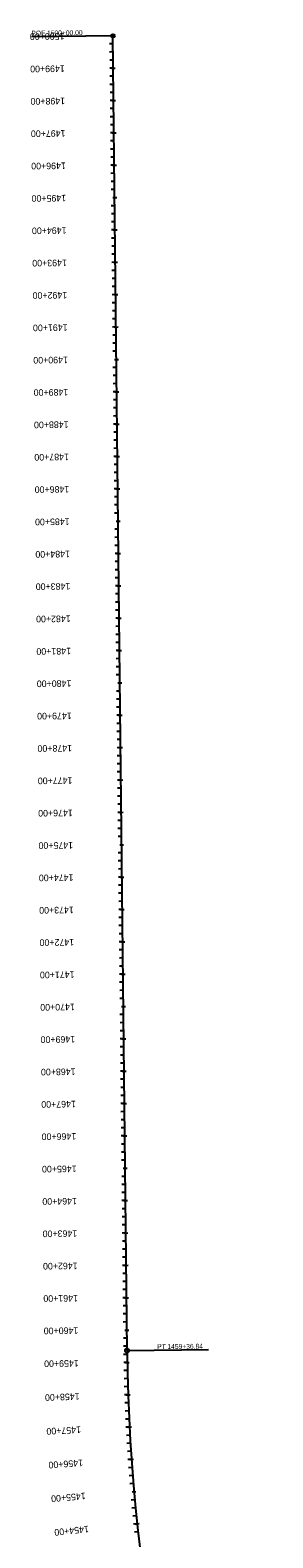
# Model space of a CAD drawing. Extents: x 20505176 to 20507193, y 7960287 to 7982631.
# Drawn here: x 20505176 to 20505926, y 7977971 to 7982631 of the extents above; entities that cross this region are included whole.
import ezdxf

# ---------------------------------------------------------------- set-up
doc = ezdxf.new("R2010")
doc.units = 0
for name, color, linetype in [('Alignment', 7, 'Continuous'), ('TextAlignment', 7, 'Continuous'), ('TextAlignmentLrg', 7, 'Continuous'), ('TextAlignmentSml', 7, 'Continuous')]:
    doc.layers.add(name, color=color, linetype=linetype)

msp = doc.modelspace()

# ---------------------------------------------------------------- linework, layer by layer
at = {"layer": 'Alignment'}
msp.add_line((20505475.7, 7978550.4), (20505432.2, 7982613.3), dxfattribs=at)
msp.add_arc((20511205.4, 7978611.7), 5730, 180.61343, 202.8772, dxfattribs=at)
at = {"layer": 'TextAlignment'}
for p, q in [((20505432.2, 7982613.3), (20505180.2, 7982610.6)), ((20505180.2, 7982610.6), (20505180.2, 7982610.6)), ((20505475.7, 7978550.4), (20505727.7, 7978553.1)), ((20505727.7, 7978553.1), (20505727.7, 7978553.1))]:
    msp.add_line(p, q, dxfattribs=at)
for centre, radius in [((20505432.2, 7982613.3), 5.34), ((20505475.7, 7978550.4), 6.24)]:
    msp.add_circle(centre, radius, dxfattribs=at)
at = {"layer": 'TextAlignmentLrg'}
for p, q in [((20505426, 7982613.2), (20505438.3, 7982613.4)), ((20505433.2, 7982513.3), (20505422.3, 7982513.2)), ((20505434.3, 7982413.3), (20505423.4, 7982413.2)), ((20505435.4, 7982313.3), (20505424.5, 7982313.2)), ((20505436.5, 7982213.3), (20505425.5, 7982213.2)), ((20505431.4, 7982113.3), (20505443.6, 7982113.4)), ((20505438.6, 7982013.3), (20505427.7, 7982013.2)), ((20505439.7, 7981913.3), (20505428.8, 7981913.2)), ((20505440.7, 7981813.3), (20505429.8, 7981813.2)), ((20505441.8, 7981713.4), (20505430.9, 7981713.2)), ((20505436.8, 7981613.3), (20505449, 7981613.4)), ((20505444, 7981513.4), (20505433, 7981513.2)), ((20505445, 7981413.4), (20505434.1, 7981413.3)), ((20505446.1, 7981313.4), (20505435.2, 7981313.3)), ((20505447.2, 7981213.4), (20505436.3, 7981213.3)), ((20505442.1, 7981113.3), (20505454.4, 7981113.5)), ((20505449.3, 7981013.4), (20505438.4, 7981013.3)), ((20505450.4, 7980913.4), (20505439.5, 7980913.3)), ((20505451.5, 7980813.4), (20505440.5, 7980813.3)), ((20505452.5, 7980713.4), (20505441.6, 7980713.3)), ((20505447.5, 7980613.3), (20505459.7, 7980613.5)), ((20505454.7, 7980513.4), (20505443.8, 7980513.3)), ((20505455.8, 7980413.4), (20505444.8, 7980413.3)), ((20505456.8, 7980313.4), (20505445.9, 7980313.3)), ((20505457.9, 7980213.4), (20505447, 7980213.3)), ((20505452.9, 7980113.4), (20505465.1, 7980113.5)), ((20505460, 7980013.4), (20505449.1, 7980013.3)), ((20505461.1, 7979913.5), (20505450.2, 7979913.3)), ((20505462.2, 7979813.5), (20505451.3, 7979813.3)), ((20505463.3, 7979713.5), (20505452.3, 7979713.3)), ((20505458.2, 7979613.4), (20505470.5, 7979613.5)), ((20505465.4, 7979513.5), (20505454.5, 7979513.4)), ((20505466.5, 7979413.5), (20505455.6, 7979413.4)), ((20505467.6, 7979313.5), (20505456.6, 7979313.4)), ((20505468.6, 7979213.5), (20505457.7, 7979213.4)), ((20505463.6, 7979113.4), (20505475.8, 7979113.6)), ((20505470.8, 7979013.5), (20505459.8, 7979013.4)), ((20505471.8, 7978913.5), (20505460.9, 7978913.4)), ((20505472.9, 7978813.5), (20505462, 7978813.4)), ((20505474, 7978713.5), (20505463.1, 7978713.4)), ((20505468.9, 7978613.5), (20505481.2, 7978613.6)), ((20505476.2, 7978513.5), (20505465.3, 7978513.3)), ((20505478.8, 7978413.6), (20505467.9, 7978413.2)), ((20505483.2, 7978313.7), (20505472.3, 7978313.1)), ((20505489.2, 7978213.9), (20505478.3, 7978213.1)), ((20505491, 7978113.6), (20505503.1, 7978114.7)), ((20505506.6, 7978014.6), (20505495.7, 7978013.5))]:
    msp.add_line(p, q, dxfattribs=at)
at = {"layer": 'TextAlignmentSml'}
for p, q in [((20505426, 7982613.2), (20505438.3, 7982613.4)), ((20505432.4, 7982588.3), (20505421.5, 7982588.2)), ((20505432.7, 7982563.3), (20505421.8, 7982563.2)), ((20505433, 7982538.3), (20505422.1, 7982538.2)), ((20505433.5, 7982488.3), (20505422.6, 7982488.2)), ((20505427.1, 7982513.2), (20505439.4, 7982513.4)), ((20505433.8, 7982463.3), (20505422.9, 7982463.2)), ((20505434, 7982438.3), (20505423.1, 7982438.2)), ((20505434.6, 7982388.3), (20505423.7, 7982388.2)), ((20505428.2, 7982413.2), (20505440.4, 7982413.4)), ((20505434.8, 7982363.3), (20505423.9, 7982363.2)), ((20505435.1, 7982338.3), (20505424.2, 7982338.2)), ((20505435.7, 7982288.3), (20505424.7, 7982288.2)), ((20505429.3, 7982313.3), (20505441.5, 7982313.4)), ((20505435.9, 7982263.3), (20505425, 7982263.2)), ((20505436.2, 7982238.3), (20505425.3, 7982238.2)), ((20505430.3, 7982213.3), (20505442.6, 7982213.4)), ((20505436.7, 7982188.3), (20505425.8, 7982188.2)), ((20505437, 7982163.3), (20505426.1, 7982163.2)), ((20505437.3, 7982138.3), (20505426.3, 7982138.2)), ((20505431.4, 7982113.3), (20505443.6, 7982113.4)), ((20505437.8, 7982088.3), (20505426.9, 7982088.2)), ((20505438.1, 7982063.3), (20505427.1, 7982063.2)), ((20505438.3, 7982038.3), (20505427.4, 7982038.2)), ((20505432.5, 7982013.3), (20505444.7, 7982013.4)), ((20505438.9, 7981988.3), (20505427.9, 7981988.2)), ((20505439.1, 7981963.3), (20505428.2, 7981963.2)), ((20505439.4, 7981938.3), (20505428.5, 7981938.2)), ((20505433.6, 7981913.3), (20505445.8, 7981913.4)), ((20505439.9, 7981888.3), (20505429, 7981888.2)), ((20505440.2, 7981863.3), (20505429.3, 7981863.2)), ((20505440.5, 7981838.3), (20505429.6, 7981838.2)), ((20505441, 7981788.3), (20505430.1, 7981788.2)), ((20505434.6, 7981813.3), (20505446.9, 7981813.4)), ((20505441.3, 7981763.3), (20505430.4, 7981763.2)), ((20505441.5, 7981738.3), (20505430.6, 7981738.2)), ((20505442.1, 7981688.4), (20505431.2, 7981688.2)), ((20505435.7, 7981713.3), (20505447.9, 7981713.4)), ((20505442.4, 7981663.4), (20505431.4, 7981663.2)), ((20505442.6, 7981638.4), (20505431.7, 7981638.2)), ((20505443.2, 7981588.4), (20505432.2, 7981588.2)), ((20505436.8, 7981613.3), (20505449, 7981613.4)), ((20505443.4, 7981563.4), (20505432.5, 7981563.2)), ((20505443.7, 7981538.4), (20505432.8, 7981538.2)), ((20505437.8, 7981513.3), (20505450.1, 7981513.4)), ((20505444.2, 7981488.4), (20505433.3, 7981488.2)), ((20505444.5, 7981463.4), (20505433.6, 7981463.2)), ((20505444.8, 7981438.4), (20505433.8, 7981438.2)), ((20505438.9, 7981413.3), (20505451.2, 7981413.4)), ((20505445.3, 7981388.4), (20505434.4, 7981388.3)), ((20505445.6, 7981363.4), (20505434.7, 7981363.3)), ((20505445.8, 7981338.4), (20505434.9, 7981338.3)), ((20505440, 7981313.3), (20505452.2, 7981313.4)), ((20505446.4, 7981288.4), (20505435.5, 7981288.3)), ((20505446.6, 7981263.4), (20505435.7, 7981263.3)), ((20505446.9, 7981238.4), (20505436, 7981238.3)), ((20505447.4, 7981188.4), (20505436.5, 7981188.3)), ((20505441.1, 7981213.3), (20505453.3, 7981213.4)), ((20505447.7, 7981163.4), (20505436.8, 7981163.3)), ((20505448, 7981138.4), (20505437.1, 7981138.3)), ((20505448.5, 7981088.4), (20505437.6, 7981088.3)), ((20505442.1, 7981113.3), (20505454.4, 7981113.5)), ((20505448.8, 7981063.4), (20505437.9, 7981063.3)), ((20505449.1, 7981038.4), (20505438.1, 7981038.3)), ((20505449.6, 7980988.4), (20505438.7, 7980988.3)), ((20505443.2, 7981013.3), (20505455.4, 7981013.5)), ((20505449.9, 7980963.4), (20505438.9, 7980963.3)), ((20505450.1, 7980938.4), (20505439.2, 7980938.3)), ((20505450.7, 7980888.4), (20505439.7, 7980888.3)), ((20505444.3, 7980913.3), (20505456.5, 7980913.5)), ((20505450.9, 7980863.4), (20505440, 7980863.3)), ((20505451.2, 7980838.4), (20505440.3, 7980838.3)), ((20505445.3, 7980813.3), (20505457.6, 7980813.5)), ((20505451.7, 7980788.4), (20505440.8, 7980788.3)), ((20505452, 7980763.4), (20505441.1, 7980763.3)), ((20505452.3, 7980738.4), (20505441.4, 7980738.3)), ((20505446.4, 7980713.3), (20505458.7, 7980713.5)), ((20505452.8, 7980688.4), (20505441.9, 7980688.3)), ((20505453.1, 7980663.4), (20505442.2, 7980663.3)), ((20505453.3, 7980638.4), (20505442.4, 7980638.3)), ((20505447.5, 7980613.3), (20505459.7, 7980613.5)), ((20505453.9, 7980588.4), (20505443, 7980588.3)), ((20505454.1, 7980563.4), (20505443.2, 7980563.3)), ((20505454.4, 7980538.4), (20505443.5, 7980538.3)), ((20505455, 7980488.4), (20505444, 7980488.3)), ((20505448.6, 7980513.4), (20505460.8, 7980513.5)), ((20505455.2, 7980463.4), (20505444.3, 7980463.3)), ((20505455.5, 7980438.4), (20505444.6, 7980438.3)), ((20505456, 7980388.4), (20505445.1, 7980388.3)), ((20505449.6, 7980413.4), (20505461.9, 7980413.5)), ((20505456.3, 7980363.4), (20505445.4, 7980363.3)), ((20505456.6, 7980338.4), (20505445.6, 7980338.3)), ((20505457.1, 7980288.4), (20505446.2, 7980288.3)), ((20505450.7, 7980313.4), (20505462.9, 7980313.5)), ((20505457.4, 7980263.4), (20505446.4, 7980263.3)), ((20505457.6, 7980238.4), (20505446.7, 7980238.3)), ((20505451.8, 7980213.4), (20505464, 7980213.5)), ((20505458.2, 7980188.4), (20505447.2, 7980188.3)), ((20505458.4, 7980163.4), (20505447.5, 7980163.3)), ((20505458.7, 7980138.4), (20505447.8, 7980138.3)), ((20505452.9, 7980113.4), (20505465.1, 7980113.5)), ((20505459.2, 7980088.4), (20505448.3, 7980088.3)), ((20505459.5, 7980063.4), (20505448.6, 7980063.3)), ((20505459.8, 7980038.4), (20505448.9, 7980038.3)), ((20505453.9, 7980013.4), (20505466.2, 7980013.5)), ((20505460.3, 7979988.4), (20505449.4, 7979988.3)), ((20505460.6, 7979963.5), (20505449.7, 7979963.3)), ((20505460.8, 7979938.5), (20505449.9, 7979938.3)), ((20505455, 7979913.4), (20505467.2, 7979913.5)), ((20505461.4, 7979888.5), (20505450.5, 7979888.3)), ((20505461.7, 7979863.5), (20505450.7, 7979863.3)), ((20505461.9, 7979838.5), (20505451, 7979838.3)), ((20505462.5, 7979788.5), (20505451.5, 7979788.3)), ((20505456.1, 7979813.4), (20505468.3, 7979813.5)), ((20505462.7, 7979763.5), (20505451.8, 7979763.3)), ((20505463, 7979738.5), (20505452.1, 7979738.3)), ((20505463.5, 7979688.5), (20505452.6, 7979688.4)), ((20505457.1, 7979713.4), (20505469.4, 7979713.5)), ((20505463.8, 7979663.5), (20505452.9, 7979663.4)), ((20505464.1, 7979638.5), (20505453.1, 7979638.4)), ((20505464.6, 7979588.5), (20505453.7, 7979588.4)), ((20505458.2, 7979613.4), (20505470.5, 7979613.5)), ((20505464.9, 7979563.5), (20505454, 7979563.4)), ((20505465.1, 7979538.5), (20505454.2, 7979538.4)), ((20505459.3, 7979513.4), (20505471.5, 7979513.5)), ((20505465.7, 7979488.5), (20505454.8, 7979488.4)), ((20505465.9, 7979463.5), (20505455, 7979463.4)), ((20505466.2, 7979438.5), (20505455.3, 7979438.4)), ((20505460.4, 7979413.4), (20505472.6, 7979413.5)), ((20505466.7, 7979388.5), (20505455.8, 7979388.4)), ((20505467, 7979363.5), (20505456.1, 7979363.4)), ((20505467.3, 7979338.5), (20505456.4, 7979338.4)), ((20505461.4, 7979313.4), (20505473.7, 7979313.6)), ((20505467.8, 7979288.5), (20505456.9, 7979288.4)), ((20505468.1, 7979263.5), (20505457.2, 7979263.4)), ((20505468.4, 7979238.5), (20505457.4, 7979238.4)), ((20505462.5, 7979213.4), (20505474.7, 7979213.6)), ((20505468.9, 7979188.5), (20505458, 7979188.4)), ((20505469.2, 7979163.5), (20505458.2, 7979163.4)), ((20505469.4, 7979138.5), (20505458.5, 7979138.4)), ((20505470, 7979088.5), (20505459, 7979088.4)), ((20505463.6, 7979113.4), (20505475.8, 7979113.6)), ((20505470.2, 7979063.5), (20505459.3, 7979063.4)), ((20505470.5, 7979038.5), (20505459.6, 7979038.4)), ((20505471, 7978988.5), (20505460.1, 7978988.4)), ((20505464.6, 7979013.4), (20505476.9, 7979013.6)), ((20505471.3, 7978963.5), (20505460.4, 7978963.4)), ((20505471.6, 7978938.5), (20505460.7, 7978938.4)), ((20505472.1, 7978888.5), (20505461.2, 7978888.4)), ((20505465.7, 7978913.4), (20505478, 7978913.6)), ((20505472.4, 7978863.5), (20505461.5, 7978863.4)), ((20505472.6, 7978838.5), (20505461.7, 7978838.4)), ((20505466.8, 7978813.5), (20505479, 7978813.6)), ((20505473.2, 7978788.5), (20505462.3, 7978788.4)), ((20505473.4, 7978763.5), (20505462.5, 7978763.4)), ((20505473.7, 7978738.5), (20505462.8, 7978738.4)), ((20505467.9, 7978713.5), (20505480.1, 7978713.6)), ((20505474.3, 7978688.5), (20505463.3, 7978688.4)), ((20505474.5, 7978663.5), (20505463.6, 7978663.4)), ((20505474.8, 7978638.5), (20505463.9, 7978638.4)), ((20505468.9, 7978613.5), (20505481.2, 7978613.6)), ((20505475.3, 7978588.5), (20505464.4, 7978588.4)), ((20505475.6, 7978563.5), (20505464.7, 7978563.4)), ((20505475.9, 7978538.5), (20505465, 7978538.4)), ((20505470.1, 7978513.4), (20505482.4, 7978513.6)), ((20505476.7, 7978488.5), (20505465.8, 7978488.3)), ((20505477.3, 7978463.5), (20505466.4, 7978463.3)), ((20505478, 7978438.6), (20505467.1, 7978438.2)), ((20505479.8, 7978388.6), (20505468.8, 7978388.2)), ((20505472.7, 7978413.4), (20505484.9, 7978413.8)), ((20505480.8, 7978363.6), (20505469.9, 7978363.1)), ((20505481.9, 7978338.6), (20505471, 7978338.1)), ((20505484.5, 7978288.7), (20505473.6, 7978288.1)), ((20505477, 7978313.3), (20505489.3, 7978314)), ((20505486, 7978263.7), (20505475.1, 7978263.1)), ((20505487.6, 7978238.8), (20505476.7, 7978238.1)), ((20505491, 7978188.9), (20505480.1, 7978188.1)), ((20505483.1, 7978213.4), (20505495.3, 7978214.3)), ((20505492.9, 7978164), (20505482, 7978163.1)), ((20505494.9, 7978139.1), (20505484, 7978138.2)), ((20505491, 7978113.6), (20505503.1, 7978114.7)), ((20505499.3, 7978089.3), (20505488.4, 7978088.3)), ((20505501.6, 7978064.4), (20505490.7, 7978063.3)), ((20505504, 7978039.5), (20505493.2, 7978038.4)), ((20505500.5, 7978014), (20505512.7, 7978015.3)), ((20505509.3, 7977989.8), (20505498.4, 7977988.6))]:
    msp.add_line(p, q, dxfattribs=at)

# ---------------------------------------------------------------- texts
at = {"layer": 'TextAlignment'}
for s, rotation, p in [('POE ', 0.6143, (20505180.1, 7982613.9)), ('1500+00.00', 0.6143, (20505228.3, 7982614.4)), ('PT', 0.6134, (20505568.8, 7978554.7)), ('1459+36.84', 0.6134, (20505600.3, 7978555))]:
    msp.add_text(s, height=15, rotation=rotation, dxfattribs=at).set_placement(p)
at = {"layer": 'TextAlignmentLrg'}
for s, rotation, p in [('1500+00', 180.6143, (20505282.1, 7982621.9)), ('1495+00', 180.6143, (20505287.4, 7982121.9)), ('1490+00', 180.6143, (20505292.8, 7981621.9)), ('1485+00', 180.6143, (20505298.1, 7981122)), ('1480+00', 180.6143, (20505303.5, 7980622)), ('1475+00', 180.6143, (20505308.9, 7980122)), ('1470+00', 180.6143, (20505314.2, 7979622.1)), ('1465+00', 180.6143, (20505319.6, 7979122.1)), ('1460+00', 180.6143, (20505325, 7978622.1)), ('1455+00', 184.9815, (20505346.7, 7978111.3))]:
    msp.add_text(s, height=20.4, rotation=rotation, dxfattribs=at).set_placement(p)
at = {"layer": 'TextAlignmentSml'}
for s, rotation, p in [('1500+00', 180.6143, (20505282.1, 7982621.9)), ('1499+00', 180.6143, (20505283.1, 7982521.9)), ('1498+00', 180.6143, (20505284.2, 7982421.9)), ('1497+00', 180.6143, (20505285.3, 7982321.9)), ('1496+00', 180.6143, (20505286.4, 7982221.9)), ('1495+00', 180.6143, (20505287.4, 7982121.9)), ('1494+00', 180.6143, (20505288.5, 7982021.9)), ('1493+00', 180.6143, (20505289.6, 7981921.9)), ('1492+00', 180.6143, (20505290.6, 7981821.9)), ('1491+00', 180.6143, (20505291.7, 7981721.9)), ('1490+00', 180.6143, (20505292.8, 7981621.9)), ('1489+00', 180.6143, (20505293.9, 7981522)), ('1488+00', 180.6143, (20505294.9, 7981422)), ('1487+00', 180.6143, (20505296, 7981322)), ('1486+00', 180.6143, (20505297.1, 7981222)), ('1485+00', 180.6143, (20505298.1, 7981122)), ('1484+00', 180.6143, (20505299.2, 7981022)), ('1483+00', 180.6143, (20505300.3, 7980922)), ('1482+00', 180.6143, (20505301.4, 7980822)), ('1481+00', 180.6143, (20505302.4, 7980722)), ('1480+00', 180.6143, (20505303.5, 7980622)), ('1479+00', 180.6143, (20505304.6, 7980522)), ('1478+00', 180.6143, (20505305.7, 7980422)), ('1477+00', 180.6143, (20505306.7, 7980322)), ('1476+00', 180.6143, (20505307.8, 7980222)), ('1475+00', 180.6143, (20505308.9, 7980122)), ('1474+00', 180.6143, (20505309.9, 7980022)), ('1473+00', 180.6143, (20505311, 7979922)), ('1472+00', 180.6143, (20505312.1, 7979822.1)), ('1471+00', 180.6143, (20505313.2, 7979722.1)), ('1470+00', 180.6143, (20505314.2, 7979622.1)), ('1469+00', 180.6143, (20505315.3, 7979522.1)), ('1468+00', 180.6143, (20505316.4, 7979422.1)), ('1467+00', 180.6143, (20505317.4, 7979322.1)), ('1466+00', 180.6143, (20505318.5, 7979222.1)), ('1465+00', 180.6143, (20505319.6, 7979122.1)), ('1464+00', 180.6143, (20505320.7, 7979022.1)), ('1463+00', 180.6143, (20505321.7, 7978922.1)), ('1462+00', 180.6143, (20505322.8, 7978822.1)), ('1461+00', 180.6143, (20505323.9, 7978722.1)), ('1460+00', 180.6143, (20505325, 7978622.1)), ('1459+00', 180.9818, (20505326.1, 7978521.2)), ('1458+00', 181.9817, (20505328.6, 7978418.6)), ('1457+00', 182.9817, (20505332.8, 7978316)), ('1456+00', 183.9816, (20505338.9, 7978213.6)), ('1455+00', 184.9815, (20505346.7, 7978111.3)), ('1454+00', 185.9814, (20505356.4, 7978009.1))]:
    msp.add_text(s, height=20.4, rotation=rotation, dxfattribs=at).set_placement(p)

doc.saveas('drawing.dxf')
